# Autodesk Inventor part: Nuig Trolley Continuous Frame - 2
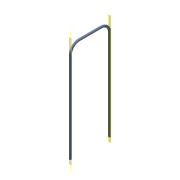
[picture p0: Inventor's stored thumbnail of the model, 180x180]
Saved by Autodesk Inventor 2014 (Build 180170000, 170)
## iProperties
Created: 2008-08
Part Number: Nuig Trolley Continuous Frame - 2
Document SubType Name: Modeling
Designer: WARREN DAVIES
Density: 1 g/cm^3
Material: Generic
Appearance: Light Steel Blue
Author: WARREN DAVIES
Title: Continous frame
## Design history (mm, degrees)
sketch "Sketch1"
  geometry: C1 r 9.525 at (0, 0); C2 r 12.7 at (0, 0); 1 further point
  constraints: 2 centre point, 2 coincident
  dimensions: "d0" = 19.05 diameter of C1; "d1" = 25.4 diameter of C2
sketch "Sketch2"
  geometry: L1 (0, 0)-(0, 1054.1); L2 (-101.6, 1155.7)-(-355.6, 1155.7); L3 (-457.2, 1054.1)-(-457.2, 0); A1 r 101.6 centre (-355.6, 1054.1) between (-355.6, 1155.7) and (-457.2, 1054.1); A2 r 101.6 centre (-101.6, 1054.1) between (0, 1054.1) and (-101.6, 1155.7); 2 further points
  constraints: 6 end point, 4 point on circle, 4 point on line, 4 tangent, 2 centre point, 2 parallel, 1 equal radius, 1 perpendicular, 1 vertical
  dimensions: "d2" = 1155.7 distance of L1.start point (0, 1155.7); "d3" = 457.2 distance of point (0, 1155.7) point (-457.2, 1155.7); "d4" = 101.6 radius of A1
sweep "Sweep1" sketch "Sketch1", "Sketch2" dims "d5" = 0
workaxis "Work Axis1"
workaxis "Work Axis2"
workplane "Work Plane1"
body "Solid1"
other parameters: "d6" = 0
